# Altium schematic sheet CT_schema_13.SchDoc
size 742 x 377 mm
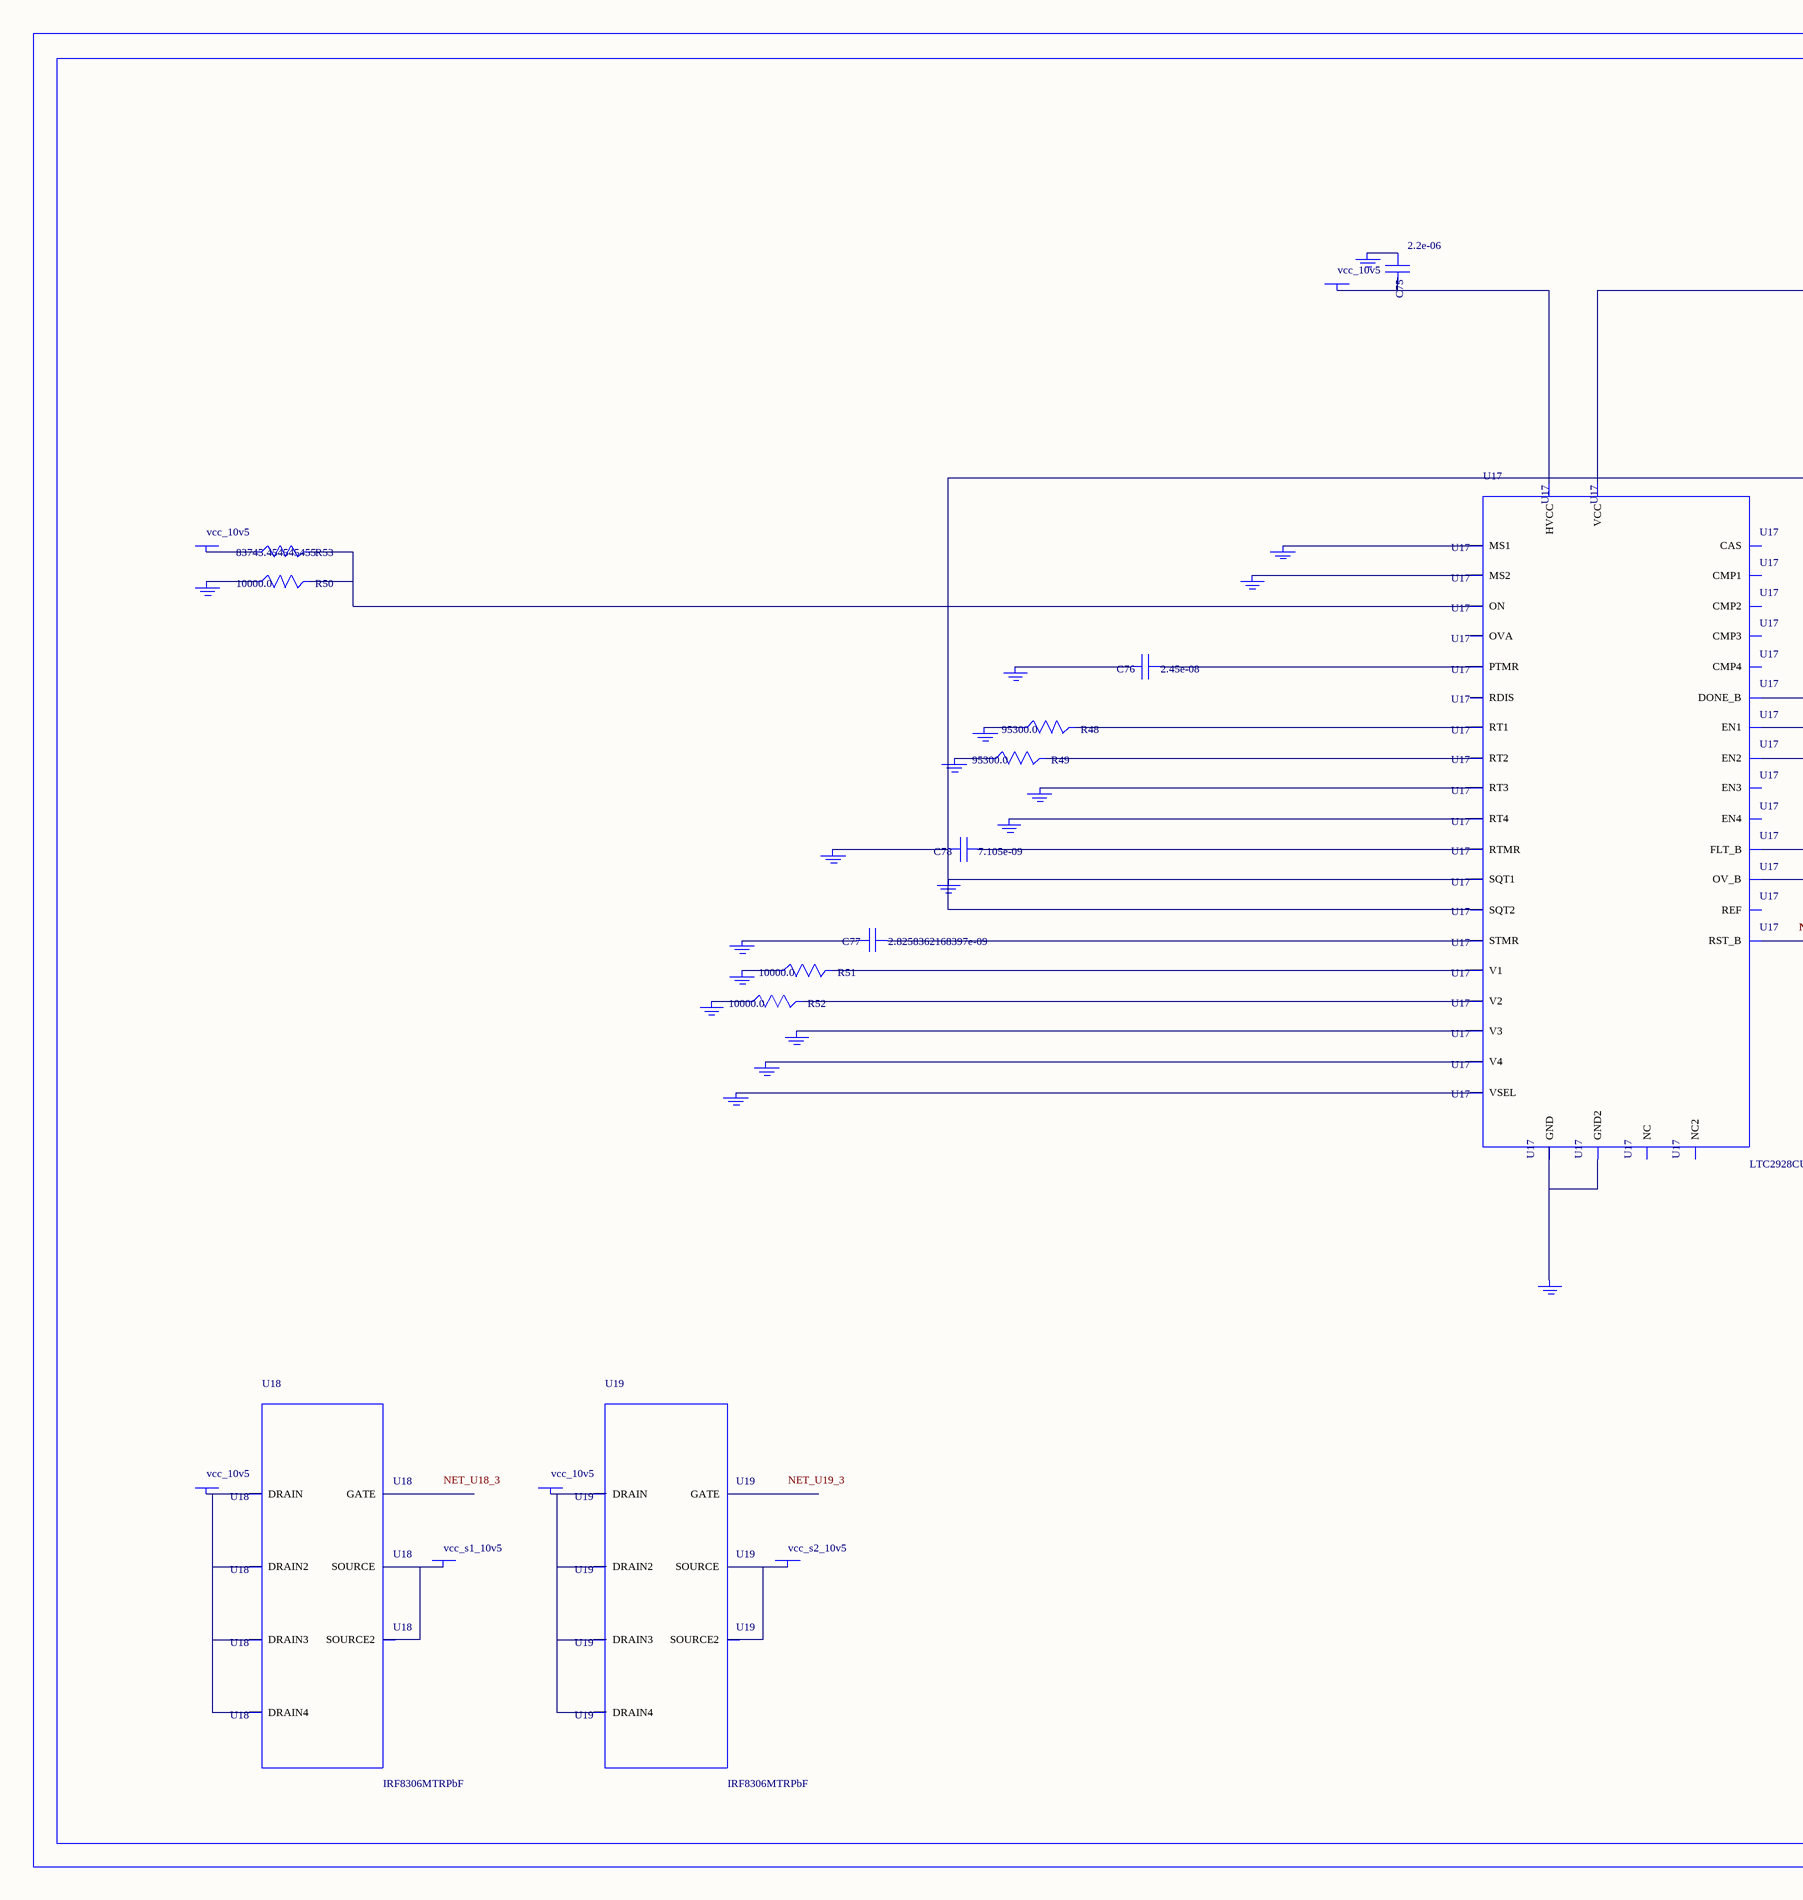
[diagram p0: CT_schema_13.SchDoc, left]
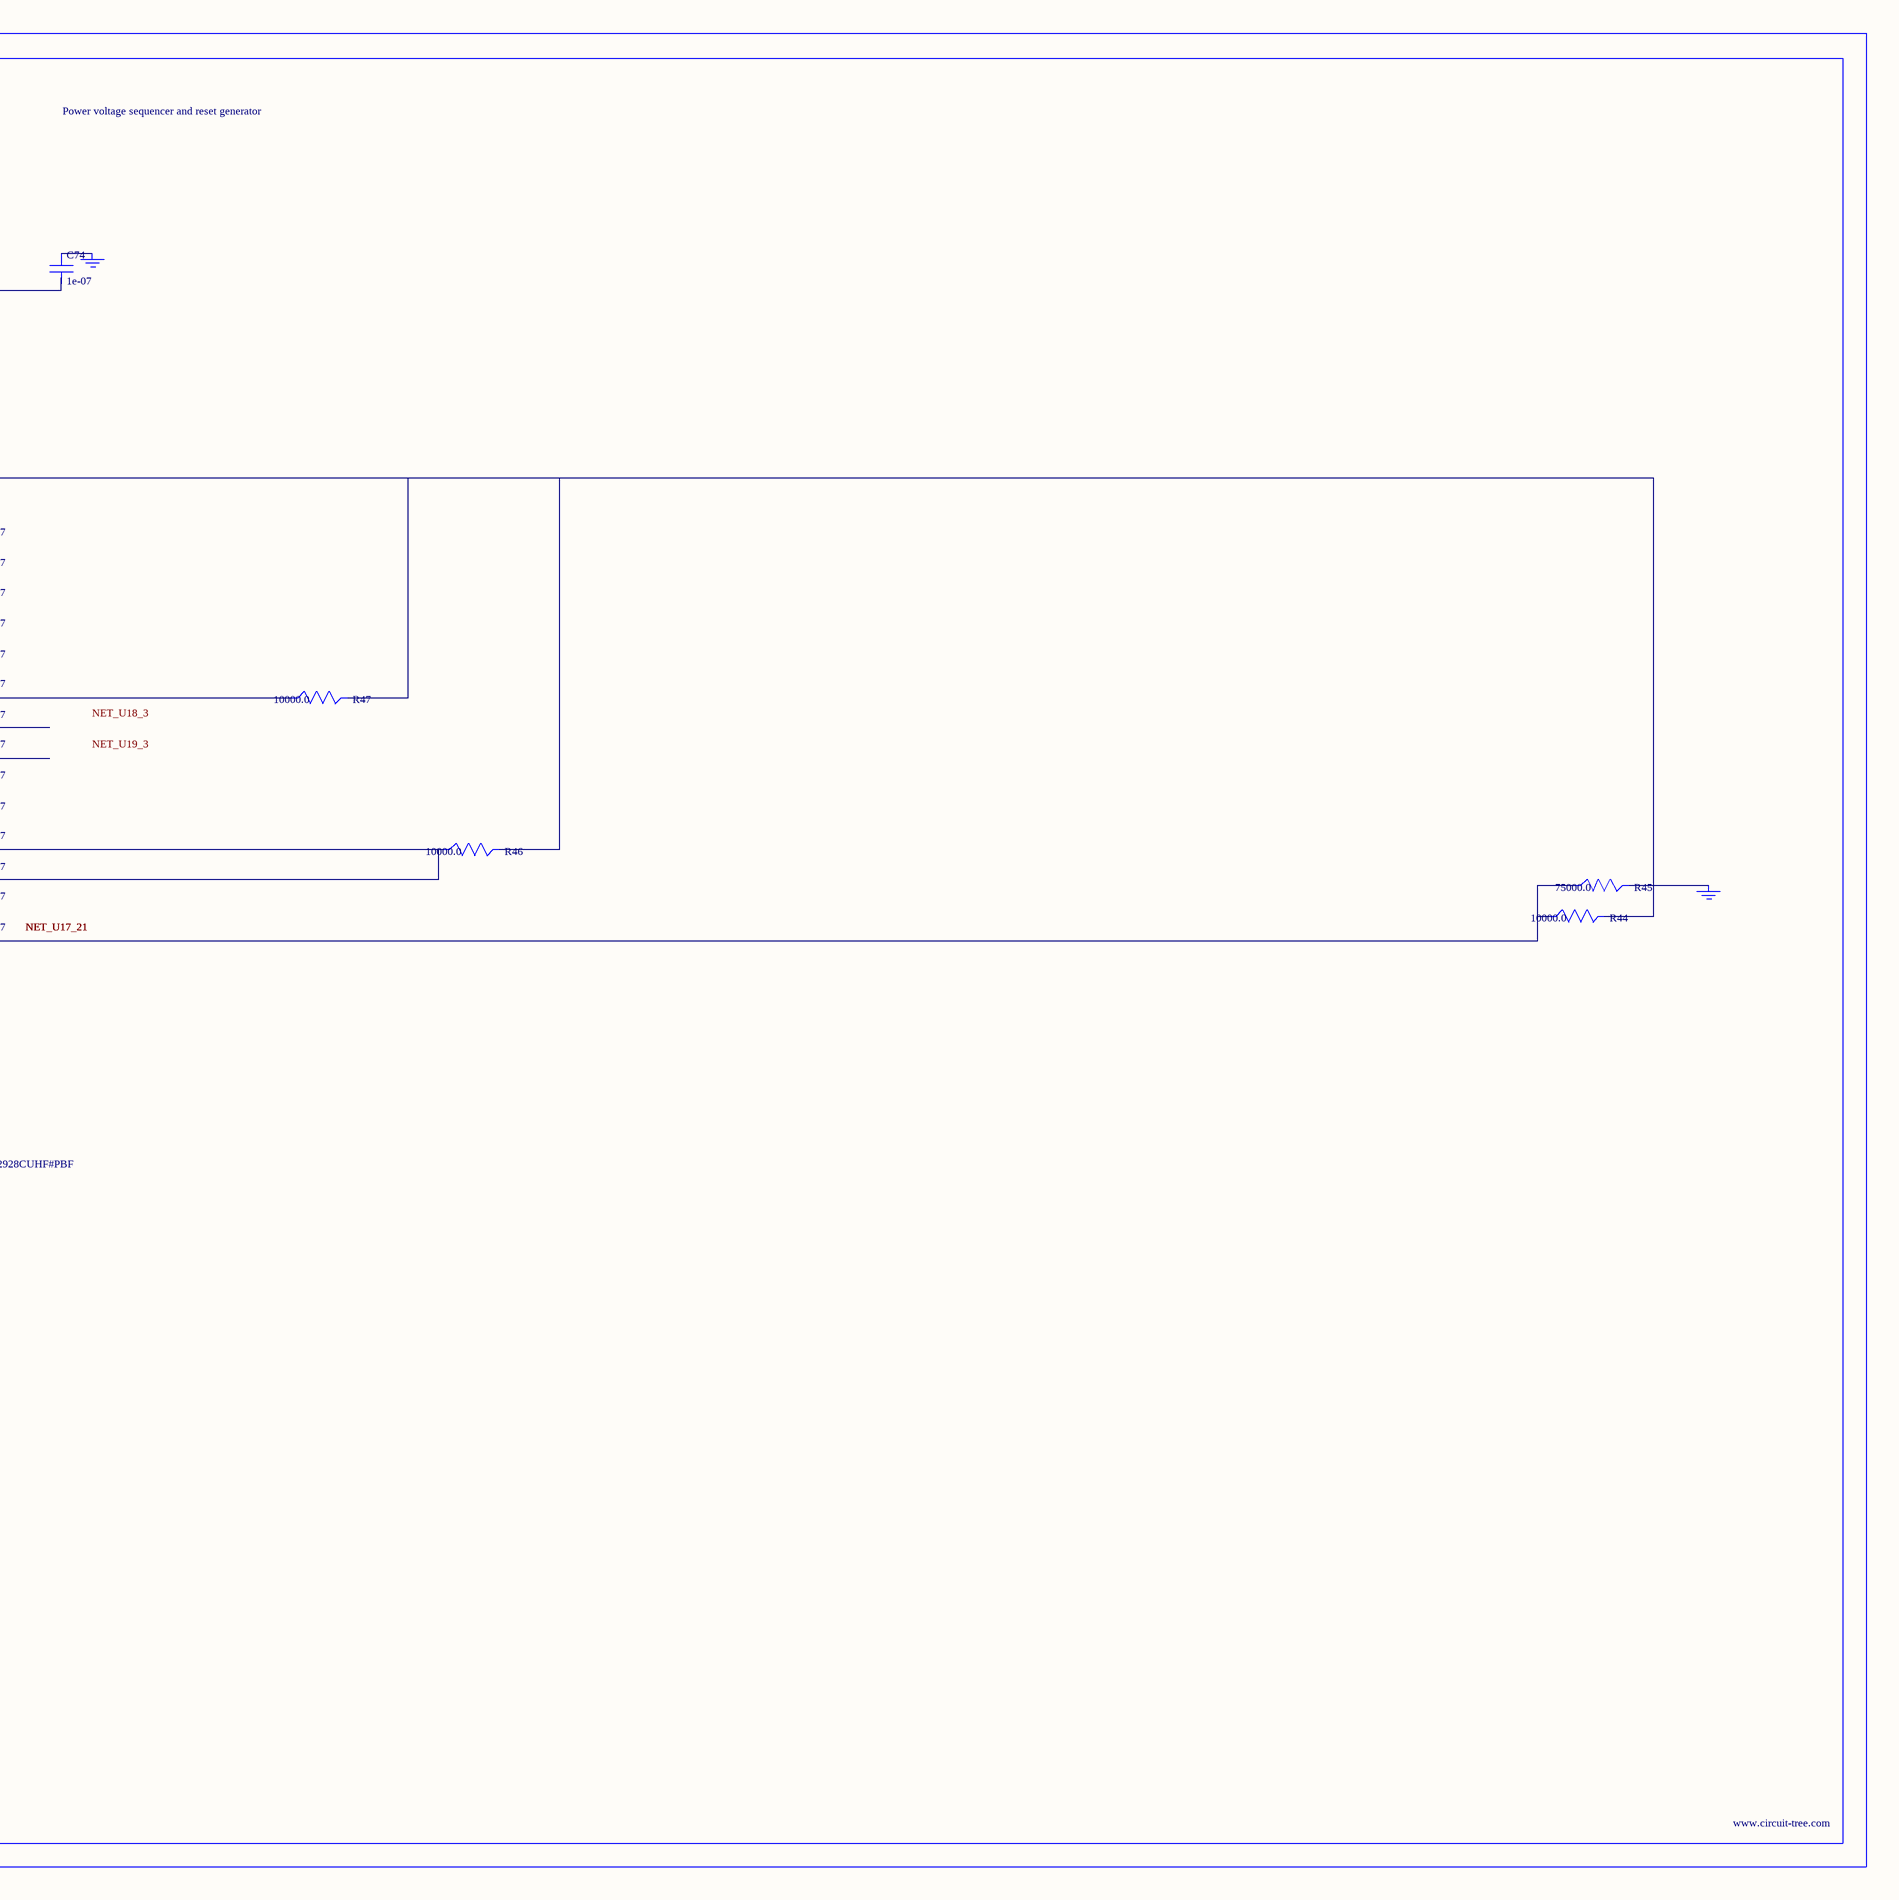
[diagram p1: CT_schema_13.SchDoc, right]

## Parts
BORDER12  (no value)
C74  1e-07  [C0402]
C75  2.2e-06  [C0603]
C76  2.45e-08  [R0603]
C77  2.8258362168397e-09  [R0603]
C78  7.105e-09  [R0603]
GND_INSTANCE_12_0  (no value)
GND_INSTANCE_12_1  (no value)
GND_INSTANCE_12_2  (no value)
GND_INSTANCE_12_3  (no value)
GND_INSTANCE_12_4  (no value)
GND_INSTANCE_12_5  (no value)
GND_INSTANCE_12_6  (no value)
GND_INSTANCE_12_7  (no value)
GND_INSTANCE_12_8  (no value)
GND_INSTANCE_12_9  (no value)
GND_INSTANCE_12_10  (no value)
GND_INSTANCE_12_11  (no value)
GND_INSTANCE_12_12  (no value)
GND_INSTANCE_12_13  (no value)
GND_INSTANCE_12_14  (no value)
GND_INSTANCE_12_15  (no value)
GND_INSTANCE_12_16  (no value)
GND_INSTANCE_12_17  (no value)
GND_INSTANCE_12_18  (no value)
GND_INSTANCE_12_19  (no value)
POWER_INSTANCE_12_0  vcc_10v5
POWER_INSTANCE_12_1  vcc_10v5
POWER_INSTANCE_12_2  vcc_10v5
POWER_INSTANCE_12_3  vcc_s1_10v5
POWER_INSTANCE_12_4  vcc_10v5
POWER_INSTANCE_12_5  vcc_s2_10v5
R44  10000.0  [R0603]
R45  75000.0  [R0603]
R46  10000.0  [R0603]
R47  10000.0  [R0603]
R48  95300.0  [R0603]
R49  95300.0  [R0603]
R50  10000.0  [R0603]
R51  10000.0  [R0603]
R52  10000.0  [R0603]
R53  83745.454545455  [R0603]
U17  LTC2928CUHF#PBF  [QFN-38_UHF]
U18  IRF8306MTRPbF  [IRF8306MTRPBF]
U19  IRF8306MTRPbF  [IRF8306MTRPBF]

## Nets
NetC74_1: C74.1 GND_INSTANCE_12_10.0(GND)
NetC74_2: C74.2 C78.2 GND_INSTANCE_12_5.0(GND) GND_INSTANCE_12_15.0(GND) R44.2 R46.2 R47.2 U17.10(SQT1) U17.11(SQT2) U17.22(VCC)
NetC75_1: C75.1 GND_INSTANCE_12_11.0(GND)
NetC75_2: C75.2 POWER_INSTANCE_12_1.0(PWR) U17.23(HVCC)
NetC76_1: C76.1 U17.27(PTMR)
NetC76_2: C76.2 GND_INSTANCE_12_14.0(GND)
NetC77_1: C77.1 U17.26(STMR)
NetC77_2: C77.2 GND_INSTANCE_12_13.0(GND)
NetC78_1: C78.1 U17.28(RTMR)
NetGND_INSTANCE_12_0_0: GND_INSTANCE_12_0.0(GND) R51.1
NetGND_INSTANCE_12_1_0: GND_INSTANCE_12_1.0(GND) R48.1
NetGND_INSTANCE_12_2_0: GND_INSTANCE_12_2.0(GND) R49.1
NetGND_INSTANCE_12_3_0: GND_INSTANCE_12_3.0(GND) U17.8(RT3)
NetGND_INSTANCE_12_4_0: GND_INSTANCE_12_4.0(GND) U17.9(RT4)
NetGND_INSTANCE_12_6_0: GND_INSTANCE_12_6.0(GND) U17.12(MS1)
NetGND_INSTANCE_12_7_0: GND_INSTANCE_12_7.0(GND) U17.13(MS2)
NetGND_INSTANCE_12_8_0: GND_INSTANCE_12_8.0(GND) R50.1
NetGND_INSTANCE_12_9_0: GND_INSTANCE_12_9.0(GND) R45.2
NetGND_INSTANCE_12_12_0: GND_INSTANCE_12_12.0(GND) U17.25(VSEL)
NetGND_INSTANCE_12_16_0: GND_INSTANCE_12_16.0(GND) U17.30(V4)
NetGND_INSTANCE_12_17_0: GND_INSTANCE_12_17.0(GND) U17.32(V3)
NetGND_INSTANCE_12_18_0: GND_INSTANCE_12_18.0(GND) R52.1
NetGND_INSTANCE_12_19_0: GND_INSTANCE_12_19.0(GND) U17.24(GND) U17.39(GND2)
NetPOWER_INSTANCE_12_0_0: POWER_INSTANCE_12_0.0(PWR) R53.1
NetPOWER_INSTANCE_12_2_0: POWER_INSTANCE_12_2.0(PWR) U18.1(DRAIN) U18.2(DRAIN2) U18.6(DRAIN3) U18.7(DRAIN4)
NetPOWER_INSTANCE_12_3_0: POWER_INSTANCE_12_3.0(PWR) U18.4(SOURCE) U18.5(SOURCE2)
NetPOWER_INSTANCE_12_4_0: POWER_INSTANCE_12_4.0(PWR) U19.1(DRAIN) U19.2(DRAIN2) U19.6(DRAIN3) U19.7(DRAIN4)
NetPOWER_INSTANCE_12_5_0: POWER_INSTANCE_12_5.0(PWR) U19.4(SOURCE) U19.5(SOURCE2)
NetR44_1: R44.1 R45.1 U17.21(RST_B)
NetR46_1: R46.1 U17.19(FLT_B) U17.20(OV_B)
NetR47_1: R47.1 U17.18(DONE_B)
NetR48_2: R48.2 U17.6(RT1)
NetR49_2: R49.2 U17.7(RT2)
NetR50_2: R50.2 R53.2 U17.16(ON)
NetR51_2: R51.2 U17.3(V1)
NetR52_2: R52.2 U17.38(V2)

Not connected (* = marked no-connect by the designer): U17 1(OVA) 2(EN1) 4(NC) 5(REF) 14(RDIS) 15(CAS) 17(NC2) 29(EN4) 31(EN3) 33(CMP3) 34(CMP4) 35(CMP1) 36(CMP2) 37(EN2); U18 3(GATE); U19 3(GATE)

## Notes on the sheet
- Labels drawn without touching a wire or pin: NET_U18_3, NET_U19_3

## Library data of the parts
BORDER12 = BORDER_PAGE12
C74 = C0402C104K3RACTU
C75 = GRM188R61H225KE1115D
C76 = C76
C77 = C77
C78 = C78
GND_INSTANCE_12_0-GND_INSTANCE_12_19 = GND
POWER_INSTANCE_12_0-POWER_INSTANCE_12_5 = PWR
R44 R46 R47 R50-R52 = RC0603JR-0710KL
R45 = RC0603JR-0775KL
R48 R49 = RC0603FR-0795K3L
R53 = R53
